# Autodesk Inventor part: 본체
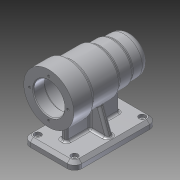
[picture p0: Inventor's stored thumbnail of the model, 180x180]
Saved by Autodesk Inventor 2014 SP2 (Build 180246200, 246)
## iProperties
Created: 2016-06
Part Number: 본체
Material: 알루미늄 6061
Document SubType Name: Modeling
Designer: 달님반
Density: 2.71 g/cm^3
Appearance: 알루미늄 - 평지
Mass: 673.898 g
Surface Area: 647.197 cm^2
Volume: 248.671 cm^3
Author: 달님반
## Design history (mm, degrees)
sketch "스케치1"
  geometry: L1 (0, 0)-(112, 0); L2 (0, 0)-(0, 25); L3 (0, 25)-(25, 25); L4 (25, 25)-(25, 27); L5 (25, 27)-(45, 27); L6 (45, 27)-(45, 30); L7 (45, 30)-(84, 30); L8 (84, 30)-(84, 34); L9 (84, 34)-(112, 34); L10 (112, 34)-(112, 0); 1 further point
  constraints: 20 end point, 4 parallel, 3 vertical, 2 perpendicular, 1 coincident, 1 horizontal
  dimensions: "d0" = 112 distance between parallel lines of L10 L2; "d1" = 84 distance between parallel lines of L2 L8; "d2" = 45 distance between parallel lines of L2 L6; "d3" = 25 distance between parallel lines of L2 L4; "d4" = 68 diameter of L9 L1; "d5" = 60 diameter of L7 L1; "d6" = 54 diameter of L5 L1; "d7" = 50 diameter of L3 L1
revolve "회전1" sketch "스케치1" stored, may be unused: angle "d8" = 90 deg
sketch "스케치2"
  geometry: L1 (0, 0)-(112, 0); L2 (112, -34)-(112, 34) reference; L3 (6, 0)-(6, 10.5); L4 (6, 10.5)-(9, 10.5); L5 (9, 10.5)-(9, 16); L6 (9, 16)-(13, 16); L7 (13, 16)-(13, 17.5); L8 (13, 17.5)-(31, 17.5); L9 (31, 17.5)-(31, 21); L10 (31, 21)-(43, 21); L11 (43, 21)-(43, 24); L12 (43, 24)-(97, 24); L13 (97, 24)-(97, 21); L14 (97, 21)-(112, 21); L15 (112, 21)-(112, 0); 1 further point
  constraints: 28 end point, 7 parallel, 2 collinear, 2 horizontal, 2 point on line, 2 vertical, 1 coincident, 1 midpoint, 1 perpendicular
  dimensions: "d9" = 42 diameter of L14 L1; "d10" = 48 diameter of L12 L1; "d11" = 42 diameter of L10 L1; "d12" = 35 diameter of L8 L1; "d13" = 32 diameter of L6 L1; "d14" = 21 diameter of L4 L1; "d15" = 3 distance of L3.end L4.end; "d16" = 15 distance of L13.end L14.end; "d17" = 54 distance of L11.end L12.end; "d18" = 12 distance of L9.end L10.end; "d19" = 18 distance of L7.end L8.end; "d20" = 4 distance of L5.end L6.end
revolve "회전2" sketch "스케치2" stored, may be unused: angle "d21" = 90 deg
node "작업 평면1"
sketch "스케치3"
  geometry: L1 (-25, 0)-(25, 0); L2 (35, 10)-(35, 102); L3 (25, 112)-(-25, 112); L4 (-35, 102)-(-35, 10); L5 (34, 112)-(-34, 112) reference; A1 r 10 centre (-25, 10) between (-35, 10) and (-25, 0); A2 r 10 centre (25, 10) between (25, 0) and (35, 10); A3 r 10 centre (25, 102) between (35, 102) and (25, 112); A4 r 10 centre (-25, 102) between (-25, 112) and (-35, 102); 6 further points
  constraints: 8 end point, 8 point on circle, 8 tangent, 6 point on line, 4 centre point, 3 equal radius, 2 midpoint, 2 parallel, 1 coincident, 1 collinear, 1 horizontal, 1 perpendicular
  dimensions: "d23" = 112 distance of point (-35, 112) point (-35, 0); "d24" = 70 distance of point (-35, 0) point (35, 0); "d25" = 10 radius of A1
extrude "돌출1" join sketch "스케치3" distance "d26" = 10; taper "d27" = 0 deg
node "작업 평면2"
sketch "스케치4"
  geometry: L1 (25, -60)-(-25, -60) reference; L2 (35, -60)-(25, -60) reference; L3 (-25, -60)-(-35, -60) reference; L4 (0, 0)-(0, -60); L5 (35, -70)-(35, -60) reference; L6 (15.509, -25.68)-(28, -60); L7 (-15.509, -25.68)-(-28, -60); L8 (-28, -60)-(28, -60); A1 r 30 centre (0, 0) between (15.509, -25.68) and (-15.509, -25.68) reference; A2 r 30 centre (0, 0) between (-15.509, -25.68) and (15.509, -25.68); 1 further point
  constraints: 8 end point, 4 point on circle, 2 point on line, 1 centre point, 1 collinear, 1 concentric, 1 midpoint, 1 other
  dimensions: "d31" = 7 distance from line of L6.end L5; "d32" = 110 deg angle of L2 L6
extrude "돌출2" join sketch "스케치4" stored distance "d33" = 8; taper "d34" = 0 deg
sketch "스케치5"
  geometry: L1 (0, -25)-(0, 25) reference; L2 (0, 25)-(25, 25) reference; L3 (25, 25)-(25, 27) reference; L4 (25, 27)-(45, 27) reference; L5 (45, 27)-(45, 30) reference; L6 (45, 30)-(84, 30) reference; L7 (84, 30)-(84, 34) reference; L8 (84, 34)-(112, 34) reference; L9 (112, 34)-(112, 21) reference; L10 (112, 21)-(97, 21) reference; L11 (97, 21)-(97, 24) reference; L12 (97, 24)-(43, 24) reference; L13 (43, 24)-(43, 21) reference; L14 (43, 21)-(31, 21) reference; L15 (31, 21)-(31, 17.5) reference; L16 (31, 17.5)-(13, 17.5) reference; L17 (13, 17.5)-(13, 16) reference; L18 (13, 16)-(9, 16) reference; L19 (9, 16)-(9, 10.5) reference; L20 (9, 10.5)-(6, 10.5) reference; L21 (6, 10.5)-(6, -10.5) reference; L22 (6, -10.5)-(9, -10.5) reference; L23 (9, -10.5)-(9, -16) reference; L24 (9, -16)-(13, -16) reference; L25 (13, -16)-(13, -17.5) reference; L26 (13, -17.5)-(31, -17.5) reference; L27 (31, -17.5)-(31, -21) reference; L28 (31, -21)-(43, -21) reference; L29 (43, -21)-(43, -24) reference; L30 (43, -24)-(97, -24) reference; L31 (97, -24)-(97, -21) reference; L32 (97, -21)-(112, -21) reference; L33 (112, -21)-(112, -34) reference; L34 (112, -34)-(84, -34) reference; L35 (84, -34)-(84, -30) reference; L36 (84, -30)-(60, -30) reference; L37 (60, -30)-(60, -60) reference; L38 (60, -60)-(112, -60) reference; L39 (112, -60)-(112, -70) reference; L40 (112, -70)-(0, -70) reference; L41 (0, -70)-(0, -60) reference; L42 (0, -60)-(52, -60) reference; L43 (52, -60)-(52, -30) reference; L44 (52, -30)-(45, -30) reference; L45 (45, -30)-(45, -27) reference; L46 (45, -27)-(25, -27) reference; L47 (25, -27)-(25, -25) reference; L48 (25, -25)-(0, -25) reference; L49 (92, -34)-(92, -60); L50 (20, -25)-(20, -60); 1 further point
  constraints: 4 end point, 4 point on line, 1 perpendicular
  dimensions: "d37" = 90 deg angle of L38 L49; "d39" = 20 distance from line of L39 L49.end; "d40" = 20 distance between parallel lines of L50 L41
  node "절단 모서리 투영1"
feature "리브1" dims "d41" = 1, "d42" = 8, "d43" = 0, "d44" = 0, "d45" = 1, "d46" = 1
feature "리브2" dims "d47" = 1, "d48" = 8, "d49" = 0, "d50" = 0, "d51" = 1, "d52" = 1
sketch "스케치6"
  geometry: C1 r 21 at (0, 0) reference; C2 r 34 at (0, 0) reference; A1 r 26 centre (0, 0) between (0, 26) and (-26, 0); 2 further points
  constraints: 4 point on circle, 2 horizontal alignment, 2 vertical alignment, 1 centre point, 1 coincident
  dimensions: "d53" = 52 diameter of A1
hole "구멍1" sketch "스케치6" at (0, 26), (-26, 0), (0, -26), (26, 0) diameter "d54" = 3.242; stored, may be unused: countersink angle "d58" = 90 deg, drill point angle "d60" = 118 deg; dims "d55" = 8, "d56" = 4, "d57" = 2, "d59" = 11
sketch "스케치7"
  geometry: A1 r 10 centre (25, 10) between (25, 0) and (35, 10) reference; A2 r 10 centre (25, 102) between (35, 102) and (25, 112) reference; A3 r 10 centre (-25, 102) between (-25, 112) and (-35, 102) reference; A4 r 10 centre (-25, 10) between (-35, 10) and (-25, 0) reference; 1 further point
hole "구멍2" sketch "스케치7" at (-25, 102), (25, 102), (-25, 10), (25, 10) diameter "d61" = 5; stored, may be unused: countersink angle "d65" = 90 deg, drill point angle "d67" = 118 deg; dims "d62" = 8, "d63" = 9, "d64" = 4, "d66" = 11
chamfer "모따기1" distance "d68" = 4; stored, may be unused: second distance "d69" = 2, angle "d70" = 45 deg
chamfer "모따기2" distance "d71" = 1; stored, may be unused: second distance "d72" = 2, angle "d73" = 45 deg
fillet "모깎기1" dims "d74" = 10
fillet "모깎기2" dims "d75" = 3
fillet "모깎기3" dims "d76" = 3
fillet "모깎기4" dims "d77" = 3
fillet "모깎기5" dims "d78" = 0.3
node "작업 평면3"
sketch "스케치8"
  geometry: L1 (10, -70)-(102, -70) reference; L2 (112, -34)-(112, 34) reference; 2 further points
  constraints: 1 other
  dimensions: "d80" = 70 distance from line of L1 point (64, 0); "d81" = 48 distance from line of L2 point (64, 0)
feature "엠보싱1" sketch "스케치8" dims "d9" = 42, "d10" = 48, "d11" = 42, "d12" = 35, "d13" = 32, "d14" = 21, "d15" = 3, "d16" = 15, "d17" = 54, "d18" = 12, "d19" = 18, "d20" = 4, "d82" = 0.5, "d83" = 0
node "솔리드1"
other parameters: "d28" = 56, "d79" = 49.5
